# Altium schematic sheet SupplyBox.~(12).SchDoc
size B; SheetNumber: 1; SheetTotal: 1
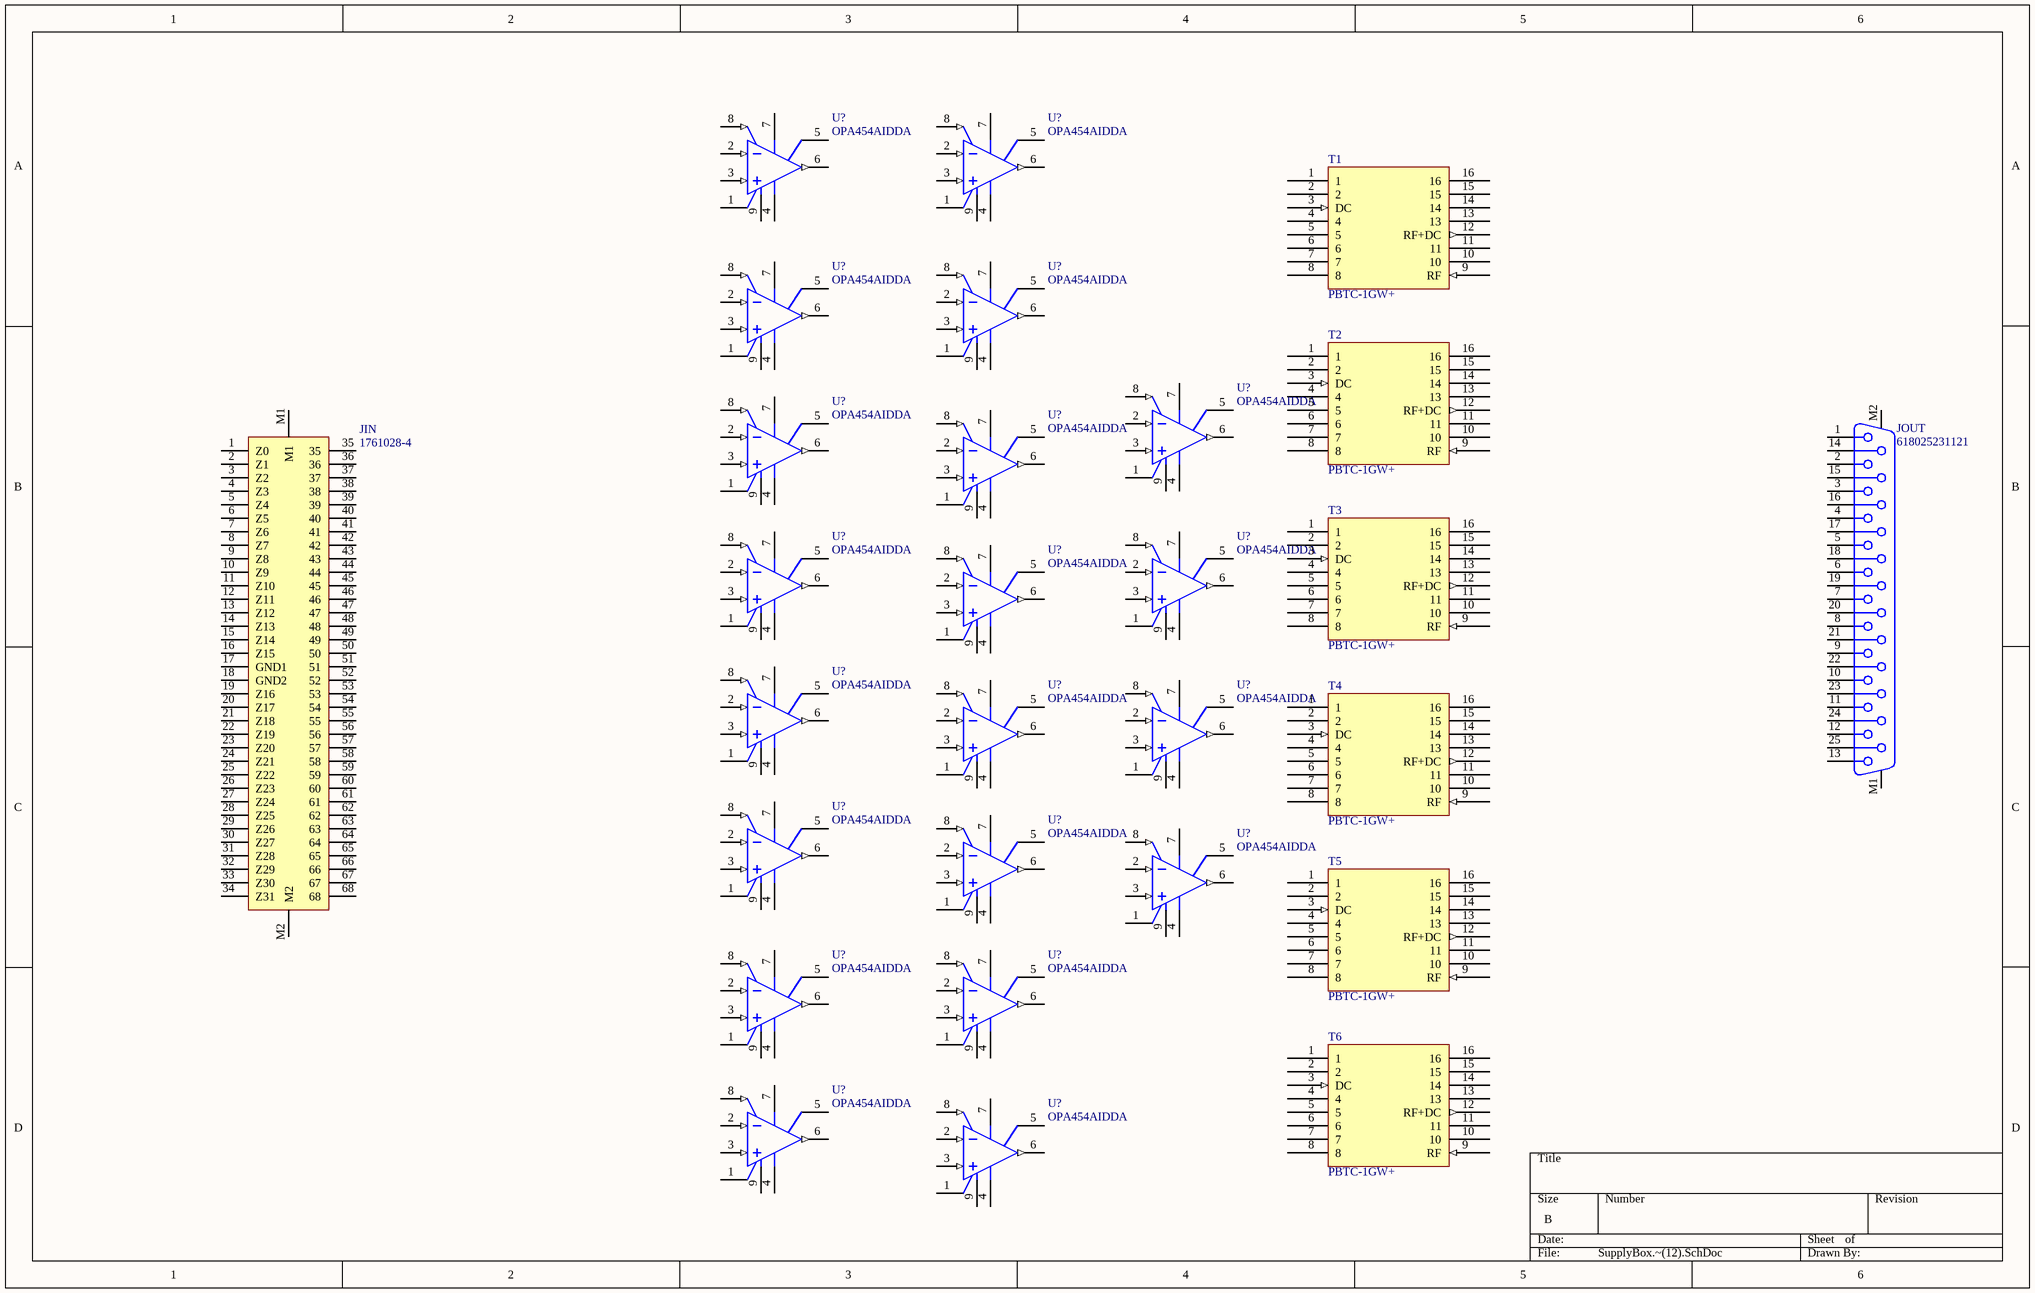
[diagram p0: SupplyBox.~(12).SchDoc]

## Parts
(Parts that share a designator on the sheet are numbered #1, #2 ... from top to bottom, then left to right.)
JIN  1761028-4  [1761028-4-Footprint-1]
JOUT  618025231121  [618025231121]
T1  PBTC-1GW+  [PBTC-1GW+]
T2  PBTC-1GW+  [PBTC-1GW+]
T3  PBTC-1GW+  [PBTC-1GW+]
T4  PBTC-1GW+  [PBTC-1GW+]
T5  PBTC-1GW+  [PBTC-1GW+]
T6  PBTC-1GW+  [PBTC-1GW+]
U?#1  OPA454AIDDA  [DDA0008C_L]
U?#2  OPA454AIDDA  [DDA0008C_L]
U?#3  OPA454AIDDA  [DDA0008C_L]
U?#4  OPA454AIDDA  [DDA0008C_L]
U?#5  OPA454AIDDA  [DDA0008C_L]
U?#6  OPA454AIDDA  [DDA0008C_L]
U?#7  OPA454AIDDA  [DDA0008C_L]
U?#8  OPA454AIDDA  [DDA0008C_L]
U?#9  OPA454AIDDA  [DDA0008C_L]
U?#10  OPA454AIDDA  [DDA0008C_L]
U?#11  OPA454AIDDA  [DDA0008C_L]
U?#12  OPA454AIDDA  [DDA0008C_L]
U?#13  OPA454AIDDA  [DDA0008C_L]
U?#14  OPA454AIDDA  [DDA0008C_L]
U?#15  OPA454AIDDA  [DDA0008C_L]
U?#16  OPA454AIDDA  [DDA0008C_L]
U?#17  OPA454AIDDA  [DDA0008C_L]
U?#18  OPA454AIDDA  [DDA0008C_L]
U?#19  OPA454AIDDA  [DDA0008C_L]
U?#20  OPA454AIDDA  [DDA0008C_L]

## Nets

Not connected (* = marked no-connect by the designer): JIN 1(Z0) 2(Z1) 3(Z2) 4(Z3) 5(Z4) 6(Z5) 7(Z6) 8(Z7) 9(Z8) 10(Z9) 11(Z10) 12(Z11) 13(Z12) 14(Z13) 15(Z14) 16(Z15) 17(GND1) 18(GND2) 19(Z16) 20(Z17) 21(Z18) 22(Z19) 23(Z20) 24(Z21) 25(Z22) 26(Z23) 27(Z24) 28(Z25) 29(Z26) 30(Z27) 31(Z28) 32(Z29) 33(Z30) 34(Z31) 35 36 37 38 39 40 41 42 43 44 45 46 47 48 49 50 51 52 53 54 55 56 57 58 59 60 61 62 63 64 65 66 67 68 M1 M2; JOUT 1 2 3 4 5 6 7 8 9 10 11 12 13 14 15 16 17 18 19 20 21 22 23 24 25 M1 M2; T1 1 2 3(DC) 4 5 6 7 8 9(RF) 10 11 12(RF+DC) 13 14 15 16; T2 1 2 3(DC) 4 5 6 7 8 9(RF) 10 11 12(RF+DC) 13 14 15 16; T3 1 2 3(DC) 4 5 6 7 8 9(RF) 10 11 12(RF+DC) 13 14 15 16; T4 1 2 3(DC) 4 5 6 7 8 9(RF) 10 11 12(RF+DC) 13 14 15 16; T5 1 2 3(DC) 4 5 6 7 8 9(RF) 10 11 12(RF+DC) 13 14 15 16; T6 1 2 3(DC) 4 5 6 7 8 9(RF) 10 11 12(RF+DC) 13 14 15 16; U?#1 1(E/D_COM) 2(IN-) 3(IN+) 4(V-) 5(STATUS_FLAG) 6(OUT) 7(V+) 8(E/D) 9(EP); U?#2 1(E/D_COM) 2(IN-) 3(IN+) 4(V-) 5(STATUS_FLAG) 6(OUT) 7(V+) 8(E/D) 9(EP); U?#3 1(E/D_COM) 2(IN-) 3(IN+) 4(V-) 5(STATUS_FLAG) 6(OUT) 7(V+) 8(E/D) 9(EP); U?#4 1(E/D_COM) 2(IN-) 3(IN+) 4(V-) 5(STATUS_FLAG) 6(OUT) 7(V+) 8(E/D) 9(EP); U?#5 1(E/D_COM) 2(IN-) 3(IN+) 4(V-) 5(STATUS_FLAG) 6(OUT) 7(V+) 8(E/D) 9(EP); U?#6 1(E/D_COM) 2(IN-) 3(IN+) 4(V-) 5(STATUS_FLAG) 6(OUT) 7(V+) 8(E/D) 9(EP); U?#7 1(E/D_COM) 2(IN-) 3(IN+) 4(V-) 5(STATUS_FLAG) 6(OUT) 7(V+) 8(E/D) 9(EP); U?#8 1(E/D_COM) 2(IN-) 3(IN+) 4(V-) 5(STATUS_FLAG) 6(OUT) 7(V+) 8(E/D) 9(EP); U?#9 1(E/D_COM) 2(IN-) 3(IN+) 4(V-) 5(STATUS_FLAG) 6(OUT) 7(V+) 8(E/D) 9(EP); U?#10 1(E/D_COM) 2(IN-) 3(IN+) 4(V-) 5(STATUS_FLAG) 6(OUT) 7(V+) 8(E/D) 9(EP); U?#11 1(E/D_COM) 2(IN-) 3(IN+) 4(V-) 5(STATUS_FLAG) 6(OUT) 7(V+) 8(E/D) 9(EP); U?#12 1(E/D_COM) 2(IN-) 3(IN+) 4(V-) 5(STATUS_FLAG) 6(OUT) 7(V+) 8(E/D) 9(EP); U?#13 1(E/D_COM) 2(IN-) 3(IN+) 4(V-) 5(STATUS_FLAG) 6(OUT) 7(V+) 8(E/D) 9(EP); U?#14 1(E/D_COM) 2(IN-) 3(IN+) 4(V-) 5(STATUS_FLAG) 6(OUT) 7(V+) 8(E/D) 9(EP); U?#15 1(E/D_COM) 2(IN-) 3(IN+) 4(V-) 5(STATUS_FLAG) 6(OUT) 7(V+) 8(E/D) 9(EP); U?#16 1(E/D_COM) 2(IN-) 3(IN+) 4(V-) 5(STATUS_FLAG) 6(OUT) 7(V+) 8(E/D) 9(EP); U?#17 1(E/D_COM) 2(IN-) 3(IN+) 4(V-) 5(STATUS_FLAG) 6(OUT) 7(V+) 8(E/D) 9(EP); U?#18 1(E/D_COM) 2(IN-) 3(IN+) 4(V-) 5(STATUS_FLAG) 6(OUT) 7(V+) 8(E/D) 9(EP); U?#19 1(E/D_COM) 2(IN-) 3(IN+) 4(V-) 5(STATUS_FLAG) 6(OUT) 7(V+) 8(E/D) 9(EP); U?#20 1(E/D_COM) 2(IN-) 3(IN+) 4(V-) 5(STATUS_FLAG) 6(OUT) 7(V+) 8(E/D) 9(EP)

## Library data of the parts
JIN = CMP-002-00071-1: Telecom and Datacom Connector, 68 Contact(s), Female, Right Angle, Solder Terminal, #2-56, Receptacle
JOUT = CMP-1502-00202-2: NexarPartId: 18818207; Pitch: 2.77mm; Operating Supply Voltage: 125V; Gender: Female; Insulation Resistance: 5GΩ; Contact Resistance: 30mΩ; Current Rating: 3A; Number of Contacts: 25
T1-T6 = CMP-00025-00003-1: Monitor TEE DC Block, 0.1MHz Min, 1000MHz Max, 1dB Insertion Loss-Max
U?#1-U?#20 = CMP-0017-00714-2: High Voltage (100V), High-Current (50mA) Operational Amplifier, G=1 Stable, 10 to 100 V, -55 to 125 degC, 8-pin SOP (DDA8), Green (RoHS & no Sb/Br); Manufacturer: Texas Instruments; Number of Channels: 1; CMRR(Min)(dB): 100; Rating: Catalog; Total Supply Voltage(Min)(+5V is 5, +/-5V is 10): 10; Offset Drift(Typ)(uV/C): 1.6; Vn at 1kHz(Typ)(nV/rtHz): 47; Slew Rate(Typ)(V/us): 13; Sub Family: General Purpose Amplifier, High Output Current Amplifier (>=50mA), High Supply Voltage Amplifier (>=30V), Precision Amplifier; Iq per channel(Max)(mA): 4; GBW(Typ)(MHz): 2.5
